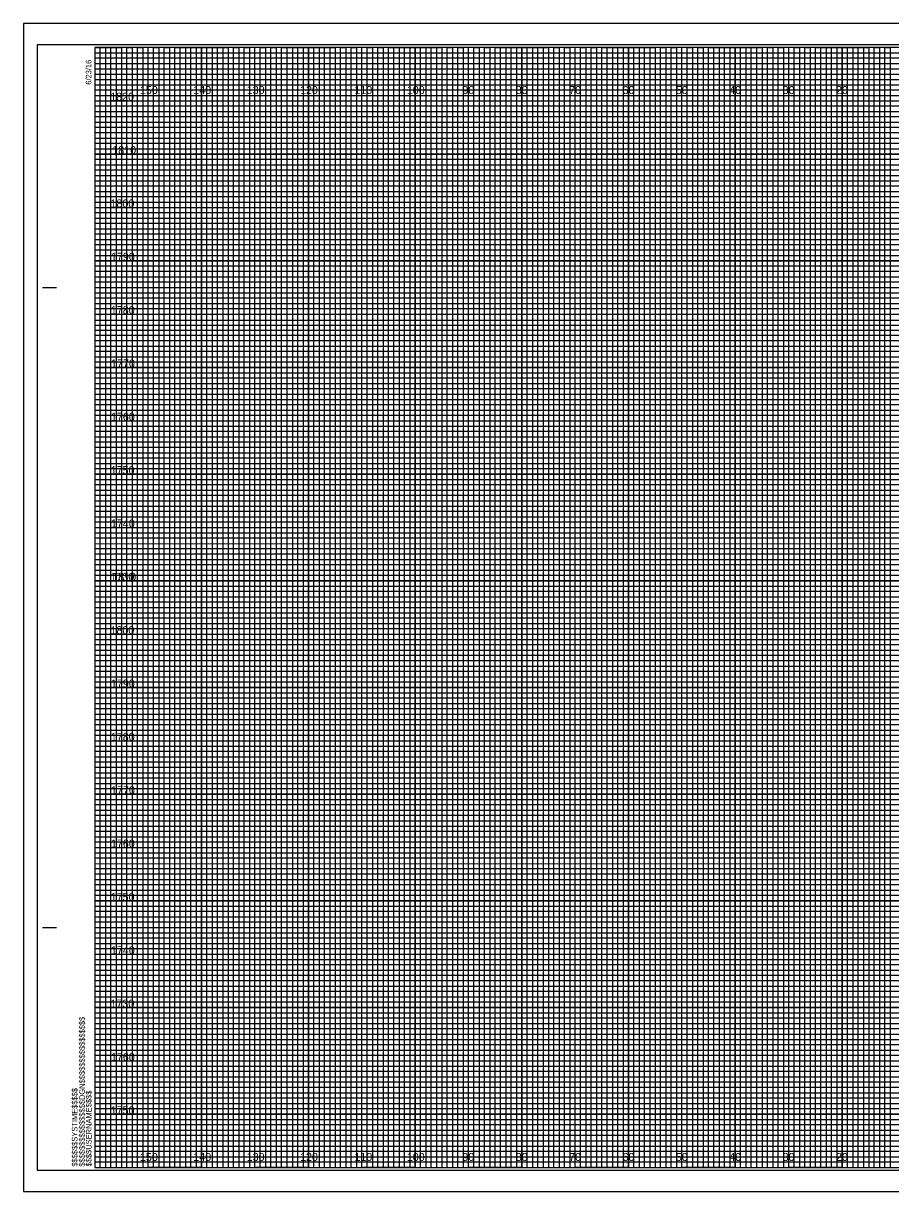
# Model space of a CAD drawing. Extents: x 791 to 1128, y -18 to 860.
# Drawn here: x 791.1 to 953.6, y -18.2 to 200.8 of the extents above; entities that cross this region are included whole.
import ezdxf

# ---------------------------------------------------------------- set-up
doc = ezdxf.new("R2010")
doc.units = 0
for name, color, linetype in [('Prop XS DDE', 7, 'Continuous'), ('Prop XS Earthwork Shape', 7, 'Continuous'), ('Raster_Level_0', 7, 'Continuous'), ('Scratch_Level_1', 7, 'Continuous'), ('Scratch_Level_3', 7, 'Continuous'), ('Sheet Cross Section CELL', 7, 'Continuous'), ('Sheet Cross Section Grid Minor 2 CELL', 7, 'Continuous'), ('Sheet Cutting Line CELL', 7, 'Continuous'), ('Sheet DOT Grid CELL', 7, 'Continuous'), ('Sheet Plot Border Inside CELL', 7, 'Continuous'), ('Sheet Plot Border Outside CELL', 7, 'Continuous')]:
    doc.layers.add(name, color=color, linetype=linetype)

msp = doc.modelspace()

# ---------------------------------------------------------------- linework, layer by layer
at = {"layer": 'Prop XS DDE'}
for p, q in [((804.53, 195.29), (1064.53, 195.29)), ((1064.53, 194.27), (804.53, 194.27)), ((804.53, 194.27), (804.53, 193.29)), ((804.53, 193.29), (1064.53, 193.29)), ((1064.53, 192.18), (804.53, 192.18)), ((804.53, 192.18), (804.53, 190.29)), ((804.53, 190.29), (1124.53, 190.29))]:
    msp.add_line(p, q, dxfattribs=at)
for points in [[(804.53, 189.29), (1074.53, 189.29), (1124.53, 189.29), (1124.53, 188.29), (804.53, 188.29)], [(804.53, 187.29), (1124.53, 187.29), (1124.53, 185.29), (804.53, 185.29)], [(804.53, 184.29), (1124.53, 184.29), (1124.53, 183.29), (804.53, 183.27)], [(804.53, 182.29), (1124.53, 182.29), (1124.53, 180.29), (804.53, 180.29)], [(804.53, 179.29), (1124.53, 179.29), (1124.53, 178.29), (804.53, 178.29)], [(804.53, 177.29), (1124.53, 177.29), (1124.53, 175.29), (804.53, 175.29)], [(804.53, 174.29), (1124.53, 174.29), (1124.53, 173.29), (804.53, 173.29)], [(804.53, 172.29), (1124.53, 172.29), (1124.53, 170.29), (804.53, 170.29)], [(804.53, 169.29), (1124.53, 169.29), (1124.53, 168.29), (804.53, 168.29)], [(804.53, 167.29), (1124.53, 167.29), (1124.53, 165.29), (804.53, 165.29)], [(804.53, 164.29), (1124.53, 164.29), (1124.53, 163.29), (804.53, 163.29)], [(804.53, 162.29), (1124.53, 162.29), (1124.53, 160.24), (1124.53, 159.29), (1124.53, 158.29), (804.53, 158.29)], [(804.53, 160.29), (1124.53, 160.29), (1124.53, 159.29), (804.53, 159.29)], [(804.53, 157.29), (1124.53, 157.29), (1124.53, 155.29), (804.53, 155.32)], [(804.53, 155.32), (1124.53, 155.29), (1124.53, 154.29), (804.53, 154.29)], [(804.53, 153.29), (1124.53, 153.29), (1124.53, 152.29), (804.53, 152.29)], [(804.53, 150.29), (1124.53, 150.29), (1124.53, 149.29), (804.53, 149.29)], [(804.53, 148.29), (1124.53, 148.29), (1124.53, 147.29), (804.53, 147.29)], [(804.46, 145.18), (1124.53, 145.18), (1124.53, 144.17), (804.46, 144.17)], [(804.53, 143.29), (1124.53, 143.29), (1124.53, 142.29), (804.53, 142.29)], [(804.53, 140.29), (1124.53, 140.29), (1124.53, 139.29), (804.53, 139.29)], [(804.53, 138.29), (1124.53, 138.29), (1124.53, 137.29), (804.53, 137.29)], [(804.53, 135.29), (1124.53, 135.29), (1124.53, 134.29), (804.53, 134.29)], [(804.53, 133.29), (1124.53, 133.29), (1124.53, 132.29), (804.53, 132.29)], [(804.53, 130.29), (1124.53, 130.29), (1124.53, 129.29), (804.53, 129.29)], [(804.53, 128.29), (1124.53, 128.29), (1124.53, 127.29), (804.53, 127.29)], [(804.53, 125.29), (1124.53, 125.29), (1124.52, 124.27), (804.53, 124.29)], [(804.53, 123.29), (1124.53, 123.29), (1124.53, 122.29), (804.53, 122.29)], [(804.53, 120.29), (1124.53, 120.29), (1124.53, 119.29), (804.53, 119.29)], [(804.53, 118.29), (1124.53, 118.29), (1124.53, 117.29), (804.53, 117.29)], [(804.53, 115.29), (1124.53, 115.29), (1124.53, 114.29), (804.53, 114.29)], [(804.53, 113.29), (1124.53, 113.29), (1124.53, 112.29), (804.53, 112.29)], [(804.53, 110.29), (1124.53, 110.29), (1124.53, 109.29), (804.53, 109.29)], [(804.53, 108.29), (1124.53, 108.29), (1124.53, 107.29), (804.53, 107.29)], [(804.53, 105.29), (1124.53, 105.29), (1124.53, 104.29), (804.53, 104.29)], [(804.53, 103.28), (1124.6, 103.2), (1124.53, 102.29), (804.53, 102.29)], [(804.53, 100.29), (1124.53, 100.29), (1124.53, 99.29), (804.53, 99.29)], [(804.53, 98.29), (1124.53, 98.29), (1124.53, 97.29), (804.53, 97.29)], [(804.53, 95.29), (1124.53, 95.29), (1124.53, 94.29), (804.53, 94.29)], [(804.53, 93.29), (1124.53, 93.29), (1124.53, 92.29), (804.53, 92.29)], [(804.53, 90.29), (1124.53, 90.29), (1124.53, 89.29), (804.53, 89.29)], [(804.53, 88.29), (1124.53, 88.29), (1124.53, 87.29), (804.53, 87.29)], [(804.53, 85.29), (1124.53, 85.29), (1124.53, 84.29), (804.53, 84.29)], [(804.53, 83.29), (1124.53, 83.29), (1124.53, 82.29), (804.53, 82.29)], [(804.53, 80.29), (1124.53, 80.29), (1124.53, 79.29), (804.53, 79.29)], [(804.53, 78.29), (1124.53, 78.29), (1124.53, 77.29), (804.53, 77.29)], [(804.53, 75.29), (1124.53, 75.29), (1124.53, 74.29), (804.53, 74.29)], [(804.53, 73.29), (1124.53, 73.29), (1124.53, 72.29), (804.53, 72.29)], [(804.53, 70.29), (1124.53, 70.29), (1124.53, 69.29), (804.53, 69.29)], [(804.53, 68.29), (1124.53, 68.29), (1124.53, 67.29), (804.53, 67.29)], [(804.53, 65.29), (1124.53, 65.29), (1124.52, 64.27), (804.53, 64.29)], [(804.53, 63.29), (1124.53, 63.29), (1124.53, 62.29), (804.53, 62.29)], [(804.53, 60.29), (1124.53, 60.29), (1124.53, 59.29), (804.53, 59.29)], [(804.53, 58.29), (1124.53, 58.29), (1124.53, 57.29), (804.53, 57.29)], [(804.53, 55.29), (1124.53, 55.29), (1124.53, 54.29), (804.53, 54.29)], [(804.53, 53.29), (1124.53, 53.29), (1124.53, 52.29), (804.53, 52.29)], [(804.53, 50.29), (1124.53, 50.29), (1124.53, 49.29), (804.53, 49.29)], [(804.53, 48.29), (1124.53, 48.29), (1124.53, 47.29), (804.53, 47.29)], [(804.53, 45.29), (1124.53, 45.29), (1124.53, 44.29), (804.53, 44.29)], [(804.53, 43.28), (1124.6, 43.2), (1124.53, 42.29), (804.53, 42.29)], [(804.53, 40.29), (1124.53, 40.29), (1124.53, 39.29), (804.53, 39.29)], [(804.53, 38.29), (1124.53, 38.29), (1124.53, 37.29), (804.53, 37.29)], [(804.53, 35.29), (1124.53, 35.29), (1124.53, 34.29), (804.53, 34.29)], [(804.53, 33.29), (1124.53, 33.29), (1124.53, 32.29), (804.53, 32.29)], [(804.53, 30.29), (1124.53, 30.29), (1124.53, 29.29), (804.53, 29.29)], [(804.53, 28.29), (1124.53, 28.29), (1124.53, 27.29), (804.53, 27.29)], [(804.53, 25.29), (1124.53, 25.29), (1124.53, 24.29), (804.53, 24.29)], [(804.53, 23.29), (1124.53, 23.29), (1124.53, 22.29), (804.53, 22.29)], [(804.53, 20.29), (1124.53, 20.29), (1124.53, 19.29), (804.53, 19.29)], [(804.53, 18.29), (1124.53, 18.29), (1124.53, 17.29), (804.53, 17.29)], [(804.53, 15.29), (1124.53, 15.29), (1124.53, 14.29), (804.53, 14.29)], [(804.53, 13.29), (1124.53, 13.29), (1124.53, 12.29), (804.53, 12.29)], [(804.53, 10.29), (1124.53, 10.29), (1124.53, 9.29), (804.53, 9.29)], [(804.53, 8.29), (1124.53, 8.29), (1124.53, 7.29), (804.53, 7.29)], [(804.53, 5.29), (1124.53, 5.29), (1124.53, 4.29), (804.53, 4.29)], [(804.53, 3.29), (1124.53, 3.29), (1124.53, 2.29), (804.53, 2.29)], [(804.53, 0.29), (1124.53, 0.29), (1124.53, -0.71), (804.53, -0.71)], [(804.53, -1.71), (1124.53, -1.71), (1124.53, -2.71), (804.53, -2.71)], [(804.53, -4.71), (1124.53, -4.71), (1124.53, -5.71), (804.53, -5.71)], [(804.53, -6.71), (1124.53, -6.71), (1124.53, -7.71), (804.53, -7.71)], [(804.53, -9.71), (1124.53, -9.71), (1124.53, -10.71), (804.53, -10.71)], [(804.53, -11.71), (1124.53, -11.71), (1124.53, -12.71), (804.53, -12.71)]]:
    msp.add_lwpolyline(points, dxfattribs=at)
at = {"layer": 'Prop XS Earthwork Shape'}
for points in [[(804.53, 196.29), (809.53, 196.29), (809.53, -13.71), (819.53, -13.71), (819.53, 196.29), (829.53, 196.29), (829.53, -13.71), (839.53, -13.71), (839.53, 196.29), (849.53, 196.29), (849.53, -13.71), (859.53, -13.71), (859.53, 196.29), (869.53, 196.29), (869.53, -13.71), (879.53, -13.71), (879.53, 196.29), (889.53, 196.29), (889.53, -13.71), (899.53, -13.71), (899.53, 196.29), (909.53, 196.29), (909.53, -13.71), (919.53, -13.71), (919.53, 196.29), (929.53, 196.29), (929.53, -13.71), (939.53, -13.71), (939.53, 196.29), (949.53, 196.29), (949.53, -13.71), (959.53, -13.71)], [(804.53, 191.29), (1079.53, 191.29)], [(804.53, 171.29), (1124.53, 171.29), (1124.53, 181.29), (804.53, 181.29)], [(804.53, 151.29), (1124.53, 151.29), (1124.53, 161.29), (804.53, 161.29)], [(804.53, 131.29), (1124.53, 131.29), (1124.53, 141.29), (804.53, 141.29)], [(804.53, 111.29), (1124.53, 111.29), (1124.53, 121.29), (804.53, 121.29)], [(804.53, 91.29), (1124.53, 91.29), (1124.53, 101.29), (804.53, 101.29)], [(804.53, 71.29), (1124.53, 71.29), (1124.53, 81.29), (804.53, 81.29)], [(804.53, 51.29), (1124.53, 51.29), (1124.53, 61.29), (804.53, 61.29)], [(804.53, 31.29), (1124.53, 31.29), (1124.53, 41.29), (804.53, 41.29)], [(804.53, 11.29), (1124.53, 11.29), (1124.53, 21.29), (804.53, 21.29)], [(804.53, -8.71), (1124.53, -8.71), (1124.53, 1.29), (804.53, 1.29)]]:
    msp.add_lwpolyline(points, dxfattribs=at)
at = {"layer": 'Scratch_Level_1'}
for p, q in [((814.53, 196.29), (804.53, 196.29)), ((814.53, -13.71), (814.53, 196.29)), ((834.53, 196.29), (824.53, 196.29)), ((824.53, 196.29), (824.53, -13.71)), ((834.53, -13.71), (834.53, 196.29)), ((854.53, 196.29), (844.53, 196.29)), ((844.53, 196.29), (844.53, -13.71)), ((854.53, -13.71), (854.53, 196.29)), ((874.53, 196.29), (864.53, 196.29)), ((864.53, 196.29), (864.53, -13.71)), ((874.53, -13.71), (874.53, 196.29)), ((894.53, 196.29), (884.53, 196.29)), ((884.53, 196.29), (884.53, -13.71)), ((894.53, -13.71), (894.53, 196.29)), ((914.53, 196.29), (904.53, 196.29)), ((904.53, 196.29), (904.53, -13.71)), ((914.53, -13.71), (914.53, 196.29)), ((934.53, 196.29), (924.53, 196.29)), ((924.53, 196.29), (924.53, -13.71)), ((934.53, -13.71), (934.53, 196.29)), ((954.53, 196.29), (944.53, 196.29)), ((944.53, 196.29), (944.53, -13.71)), ((824.53, -13.71), (814.53, -13.71)), ((844.53, -13.71), (834.53, -13.71)), ((864.53, -13.71), (854.53, -13.71)), ((884.53, -13.71), (874.53, -13.71)), ((904.53, -13.71), (894.53, -13.71)), ((924.53, -13.71), (914.53, -13.71)), ((944.53, -13.71), (934.53, -13.71))]:
    msp.add_line(p, q, dxfattribs=at)
for points in [[(804.53, 186.29), (1124.53, 186.29), (1124.53, 176.29), (804.53, 176.29)], [(804.53, 166.29), (1124.53, 166.29), (1124.53, 156.29), (804.53, 156.29)], [(804.53, 146.29), (1124.53, 146.29), (1124.53, 136.29), (804.53, 136.29)], [(804.53, 126.29), (1124.53, 126.29), (1124.53, 116.29), (804.53, 116.29)], [(804.53, 106.29), (1124.53, 106.29), (1124.53, 96.29), (804.53, 96.29)], [(804.53, 86.29), (1124.53, 86.29), (1124.53, 76.29), (804.53, 76.29)], [(804.53, 66.29), (1124.53, 66.29), (1124.53, 56.29), (804.53, 56.29)], [(804.53, 46.29), (1124.53, 46.29), (1124.53, 36.29), (804.53, 36.29)], [(804.53, 26.29), (1124.53, 26.29), (1124.53, 16.29), (804.53, 16.29)], [(804.53, 6.29), (1124.53, 6.29), (1124.53, -3.71), (804.53, -3.71)]]:
    msp.add_lwpolyline(points, dxfattribs=at)
at = {"layer": 'Sheet Cross Section CELL'}
for p, q in [((794.73, 151.29), (797.23, 151.29)), ((794.83, 151.29), (797.33, 151.29)), ((794.73, 31.29), (797.23, 31.29)), ((794.83, 31.29), (797.33, 31.29)), ((804.53, -13.71), (804.53, -13.71)), ((804.53, -13.71), (804.53, -13.71)), ((804.53, -13.71), (804.53, -13.71)), ((804.53, -13.71), (804.53, -13.71)), ((804.53, -13.71), (804.53, -13.71)), ((804.53, -13.71), (804.53, -13.71)), ((804.53, -13.71), (804.53, -13.71))]:
    msp.add_line(p, q, dxfattribs=at)
msp.add_lwpolyline([(1124.53, 196.29), (804.53, 196.29), (804.53, -13.71), (1124.53, -13.71)], close=True, dxfattribs=at)
at = {"layer": 'Sheet Cross Section Grid Minor 2 CELL'}
for points in [[(804.53, -13.71), (805.53, -13.71), (805.53, 196.29), (806.53, 196.29), (806.53, -13.71)], [(806.53, -13.71), (807.53, -13.71), (807.53, 196.29), (808.53, 196.29), (808.53, -13.71)], [(809.53, -13.71), (810.53, -13.71), (810.53, 196.29), (811.53, 196.29), (811.53, -13.71)], [(811.53, -13.71), (812.53, -13.71), (812.53, 196.29), (813.53, 196.29), (813.53, -13.71)], [(814.53, -13.71), (815.53, -13.71), (815.53, 196.29), (816.53, 196.29), (816.53, -13.71)], [(816.53, -13.71), (817.53, -13.71), (817.53, 196.29), (818.53, 196.29), (818.53, -13.71)], [(819.53, -13.71), (820.53, -13.71), (820.53, 196.29), (821.53, 196.29), (821.53, -13.71)], [(821.53, -13.71), (822.53, -13.71), (822.53, 196.29), (823.53, 196.29), (823.53, -13.71)], [(824.53, -13.71), (825.53, -13.71), (825.53, 196.29), (826.53, 196.29), (826.53, -13.71)], [(826.53, -13.71), (827.53, -13.71), (827.53, 196.29), (828.53, 196.29), (828.53, -13.71)], [(829.53, -13.71), (830.53, -13.71), (830.53, 196.29), (831.53, 196.29), (831.53, -13.71)], [(831.53, -13.71), (832.53, -13.71), (832.53, 196.29), (833.53, 196.29), (833.53, -13.71)], [(834.53, -13.71), (835.53, -13.71), (835.53, 196.29), (836.53, 196.29), (836.53, -13.71)], [(836.53, -13.71), (837.53, -13.71), (837.53, 196.29), (838.53, 196.29), (838.53, -13.71)], [(839.53, -13.71), (840.53, -13.71), (840.53, 196.29), (841.53, 196.29), (841.53, -13.71)], [(841.53, -13.71), (842.53, -13.71), (842.53, 196.29), (843.53, 196.29), (843.53, -13.71)], [(844.53, -13.71), (845.53, -13.71), (845.53, 196.29), (846.53, 196.29), (846.53, -13.71)], [(846.53, -13.71), (847.53, -13.71), (847.53, 196.29), (848.53, 196.29), (848.53, -13.71)], [(849.53, -13.71), (850.53, -13.71), (850.53, 196.29), (851.53, 196.29), (851.53, -13.71)], [(851.53, -13.71), (852.53, -13.71), (852.53, 196.29), (853.53, 196.29), (853.53, -13.71)], [(854.53, -13.71), (855.53, -13.71), (855.53, 196.29), (856.53, 196.29), (856.53, -13.71)], [(856.53, -13.71), (857.53, -13.71), (857.53, 196.29), (858.53, 196.29), (858.53, -13.71)], [(859.53, -13.71), (860.53, -13.71), (860.53, 196.29), (861.53, 196.29), (861.53, -13.71)], [(861.53, -13.71), (862.53, -13.71), (862.53, 196.29), (863.53, 196.29), (863.53, -13.71)], [(864.53, -13.71), (865.53, -13.71), (865.53, 196.29), (866.53, 196.29), (866.53, -13.71)], [(866.53, -13.71), (867.53, -13.71), (867.53, 196.29), (868.53, 196.29), (868.53, -13.71)], [(869.53, -13.71), (870.53, -13.71), (870.53, 196.29), (871.53, 196.29), (871.53, -13.71)], [(871.53, -13.71), (872.53, -13.71), (872.53, 196.29), (873.53, 196.29), (873.53, -13.71)], [(874.53, -13.71), (875.53, -13.71), (875.53, 196.29), (876.53, 196.29), (876.53, -13.71)], [(876.53, -13.71), (877.53, -13.71), (877.53, 196.29), (878.53, 196.29), (878.53, -13.71)], [(879.53, -13.71), (880.53, -13.71), (880.53, 196.29), (881.53, 196.29), (881.53, -13.71)], [(881.53, -13.71), (882.53, -13.71), (882.53, 196.29), (883.53, 196.29), (883.53, -13.71)], [(884.53, -13.71), (885.53, -13.71), (885.53, 196.29), (886.53, 196.29), (886.53, -13.71)], [(886.53, -13.71), (887.53, -13.71), (887.53, 196.29), (888.53, 196.29), (888.53, -13.71)], [(889.53, -13.71), (890.53, -13.71), (890.53, 196.29), (891.53, 196.29), (891.53, -13.71)], [(891.53, -13.71), (892.53, -13.71), (892.53, 196.29), (893.53, 196.29), (893.53, -13.71)], [(894.53, -13.71), (895.53, -13.71), (895.53, 196.29), (896.53, 196.29), (896.53, -13.71)], [(896.53, -13.71), (897.53, -13.71), (897.53, 196.29), (898.53, 196.29), (898.53, -13.71)], [(899.53, -13.71), (900.53, -13.71), (900.53, 196.29), (901.53, 196.29), (901.53, -13.71)], [(901.53, -13.71), (902.53, -13.71), (902.53, 196.29), (903.53, 196.29), (903.53, -13.71)], [(904.53, -13.71), (905.53, -13.71), (905.53, 196.29), (906.53, 196.29), (906.53, -13.71)], [(906.53, -13.71), (907.53, -13.71), (907.53, 196.29), (908.53, 196.29), (908.53, -13.71)], [(909.53, -13.71), (910.53, -13.71), (910.53, 196.29), (911.53, 196.29), (911.53, -13.71)], [(911.53, -13.71), (912.53, -13.71), (912.53, 196.29), (913.53, 196.29), (913.53, -13.71)], [(914.53, -13.71), (915.53, -13.71), (915.53, 196.29), (916.53, 196.29), (916.53, -13.71)], [(916.53, -13.71), (917.53, -13.71), (917.53, 196.29), (918.53, 196.29), (918.53, -13.71)], [(919.53, -13.71), (920.53, -13.71), (920.53, 196.29), (921.53, 196.29), (921.53, -13.71)], [(921.53, -13.71), (922.53, -13.71), (922.53, 196.29), (923.53, 196.29), (923.53, -13.71)], [(924.53, -13.71), (925.53, -13.71), (925.53, 196.29), (926.53, 196.29), (926.53, -13.71)], [(926.53, -13.71), (927.53, -13.71), (927.53, 196.29), (928.53, 196.29), (928.53, -13.71)], [(929.53, -13.71), (930.53, -13.71), (930.53, 196.29), (931.53, 196.29), (931.53, -13.71)], [(931.53, -13.71), (932.53, -13.71), (932.53, 196.29), (933.53, 196.29), (933.53, -13.71)], [(934.53, -13.71), (935.53, -13.71), (935.53, 196.29), (936.53, 196.29), (936.53, -13.71)], [(936.53, -13.71), (937.53, -13.71), (937.53, 196.29), (938.53, 196.29), (938.53, -13.71)], [(939.53, -13.71), (940.53, -13.71), (940.53, 196.29), (941.53, 196.29), (941.53, -13.71)], [(941.53, -13.71), (942.53, -13.71), (942.53, 196.29), (943.53, 196.29), (943.53, -13.71)], [(944.53, -13.71), (945.53, -13.71), (945.53, 196.29), (946.53, 196.29), (946.53, -13.71)], [(946.53, -13.71), (947.53, -13.71), (947.53, 196.29), (948.53, 196.29), (948.53, -13.71)], [(949.53, -13.71), (950.53, -13.71), (950.53, 196.29), (951.53, 196.29), (951.53, -13.71)], [(951.53, -13.71), (952.53, -13.71), (952.53, 196.29), (953.53, 196.29), (953.53, -13.71)]]:
    msp.add_lwpolyline(points, dxfattribs=at)
at = {"layer": 'Sheet Cutting Line CELL'}
for p, q in [((1127.83, 200.79), (791.13, 200.79)), ((791.13, 200.79), (791.13, -18.21)), ((791.13, -18.21), (1127.83, -18.21))]:
    msp.add_line(p, q, dxfattribs=at)
at = {"layer": 'Sheet DOT Grid CELL'}
for p, q in [((814.53, -13.71), (814.53, 196.29)), ((824.53, -13.71), (824.53, 196.29)), ((834.53, -13.71), (834.53, 196.29)), ((844.53, -13.71), (844.53, 196.29)), ((854.53, -13.71), (854.53, 196.29)), ((864.53, -13.71), (864.53, 196.29)), ((874.53, -13.71), (874.53, 196.29)), ((884.53, -13.71), (884.53, 196.29)), ((894.53, -13.71), (894.53, 196.29)), ((904.53, -13.71), (904.53, 196.29)), ((914.53, -13.71), (914.53, 196.29)), ((924.53, -13.71), (924.53, 196.29)), ((934.53, -13.71), (934.53, 196.29)), ((944.53, -13.71), (944.53, 196.29)), ((804.53, 186.29), (1124.53, 186.29)), ((804.53, 176.29), (1124.53, 176.29)), ((804.53, 166.29), (1124.53, 166.29)), ((804.53, 156.29), (1124.53, 156.29)), ((804.53, 146.29), (1124.53, 146.29)), ((804.53, 136.29), (1124.53, 136.29)), ((804.53, 126.29), (1124.53, 126.29)), ((804.53, 116.29), (1124.53, 116.29)), ((804.53, 106.29), (1124.53, 106.29)), ((804.53, 96.29), (1124.53, 96.29)), ((804.53, 86.29), (1124.53, 86.29)), ((804.53, 76.29), (1124.53, 76.29)), ((804.53, 66.29), (1124.53, 66.29)), ((804.53, 56.29), (1124.53, 56.29)), ((804.53, 46.29), (1124.53, 46.29)), ((804.53, 36.29), (1124.53, 36.29)), ((804.53, 26.29), (1124.53, 26.29)), ((804.53, 16.29), (1124.53, 16.29)), ((804.53, 6.29), (1124.53, 6.29)), ((804.53, -3.71), (1124.53, -3.71))]:
    msp.add_line(p, q, dxfattribs=at)
at = {"layer": 'Sheet Plot Border Inside CELL'}
msp.add_lwpolyline([(793.73, -14.21), (1126.93, -14.21), (1126.93, 196.79), (793.73, 196.79)], close=True, dxfattribs=at)
at = {"layer": 'Sheet Plot Border Outside CELL'}
msp.add_lwpolyline([(791.13, -18.21), (1127.83, -18.21), (1127.83, 200.79), (791.13, 200.79)], close=True, dxfattribs=at)

# ---------------------------------------------------------------- texts
at = {"layer": 'Raster_Level_0'}
for s, p in [('150', (812.98, 187.54)), ('140', (822.98, 187.54)), ('130', (832.98, 187.54)), ('120', (842.98, 187.54)), ('110', (853.16, 187.54)), ('100', (862.98, 187.54)), ('90', (873.39, 187.54)), ('80', (883.39, 187.54)), ('70', (893.39, 187.54)), ('60', (903.39, 187.54)), ('50', (913.39, 187.54)), ('40', (923.39, 187.54)), ('30', (933.39, 187.54)), ('20', (943.39, 187.54)), ('150', (812.98, -12.46)), ('140', (822.98, -12.46)), ('130', (832.98, -12.46)), ('120', (842.98, -12.46)), ('110', (853.16, -12.46)), ('100', (862.98, -12.46)), ('90', (873.39, -12.46)), ('80', (883.39, -12.46)), ('70', (893.39, -12.46)), ('60', (903.39, -12.46)), ('50', (913.39, -12.46)), ('40', (923.39, -12.46)), ('30', (933.39, -12.46)), ('20', (943.39, -12.46))]:
    msp.add_text(s, height=1.5, dxfattribs=at).set_placement(p)
at = {"layer": 'Scratch_Level_3'}
for s, p in [('1820', (807.41, 186.29)), ('1810', (807.79, 176.29)), ('1800', (807.46, 166.29)), ('1790', (807.54, 156.29)), ('1780', (807.52, 146.29)), ('1770', (807.57, 136.29)), ('1760', (807.54, 126.29)), ('1750', (807.49, 116.29)), ('1740', (807.54, 106.29)), ('1730', (807.46, 96.29)), ('1810', (807.79, 96.29)), ('1800', (807.46, 86.29)), ('1790', (807.54, 76.29)), ('1780', (807.52, 66.29)), ('1770', (807.57, 56.29)), ('1760', (807.54, 46.29)), ('1750', (807.49, 36.29)), ('1740', (807.54, 26.29)), ('1730', (807.46, 16.29)), ('1760', (807.54, 6.29)), ('1750', (807.49, -3.71))]:
    msp.add_text(s, height=1.5, dxfattribs=at).set_placement(p)
at = {"layer": 'Sheet Cross Section CELL'}
for s, p in [('6/23/16', (803.88, 189.29)), ('$$$$$$$$$$$$$$$$DGN$$$$$$$$$$$$$$$$', (802.65, -13.53)), ('$$$$$$SYSTIME$$$$$', (801.27, -13.53)), ('$$$$USERNAME$$$$', (803.91, -13.48))]:
    msp.add_text(s, height=1.05, rotation=90, dxfattribs=at).set_placement(p)

doc.saveas('drawing.dxf')
